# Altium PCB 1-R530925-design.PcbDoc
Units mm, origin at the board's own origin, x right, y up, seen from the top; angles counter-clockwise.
Board outline 53.27 x 52.14 mm, 4 copper layers (Top Layer, Mid-Layer 1, Mid-Layer 2, Bottom Layer); 97 components, 88 nets, 315 pads, 181 vias.
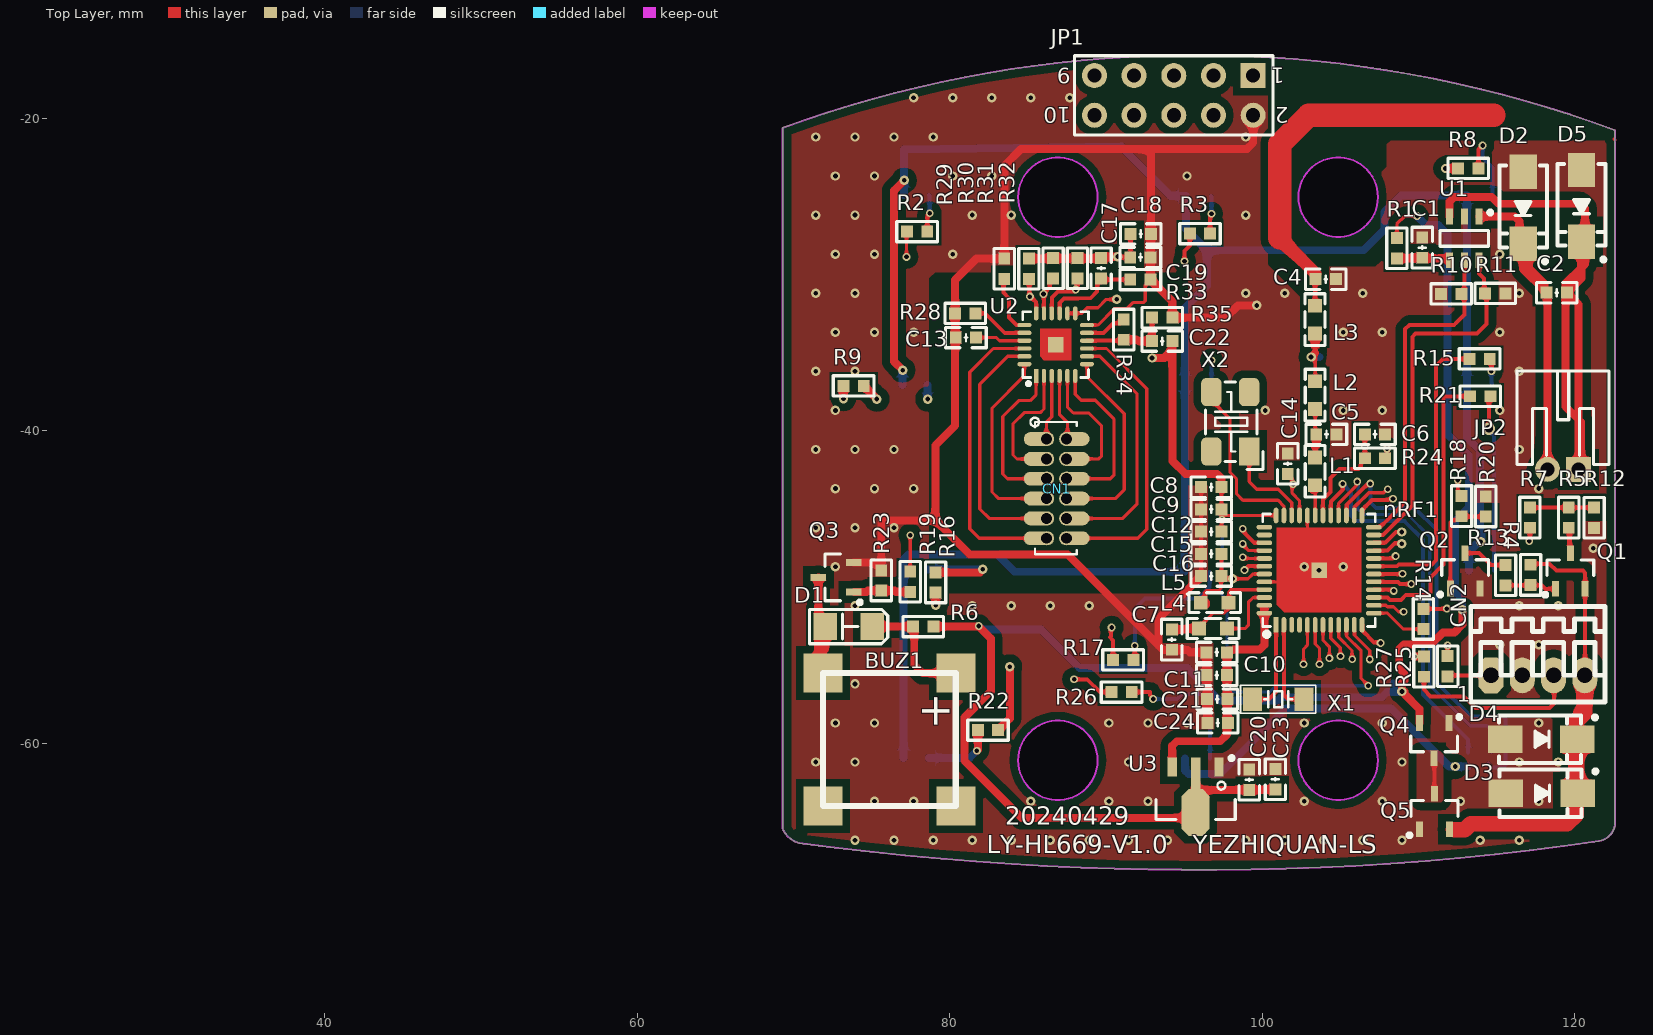
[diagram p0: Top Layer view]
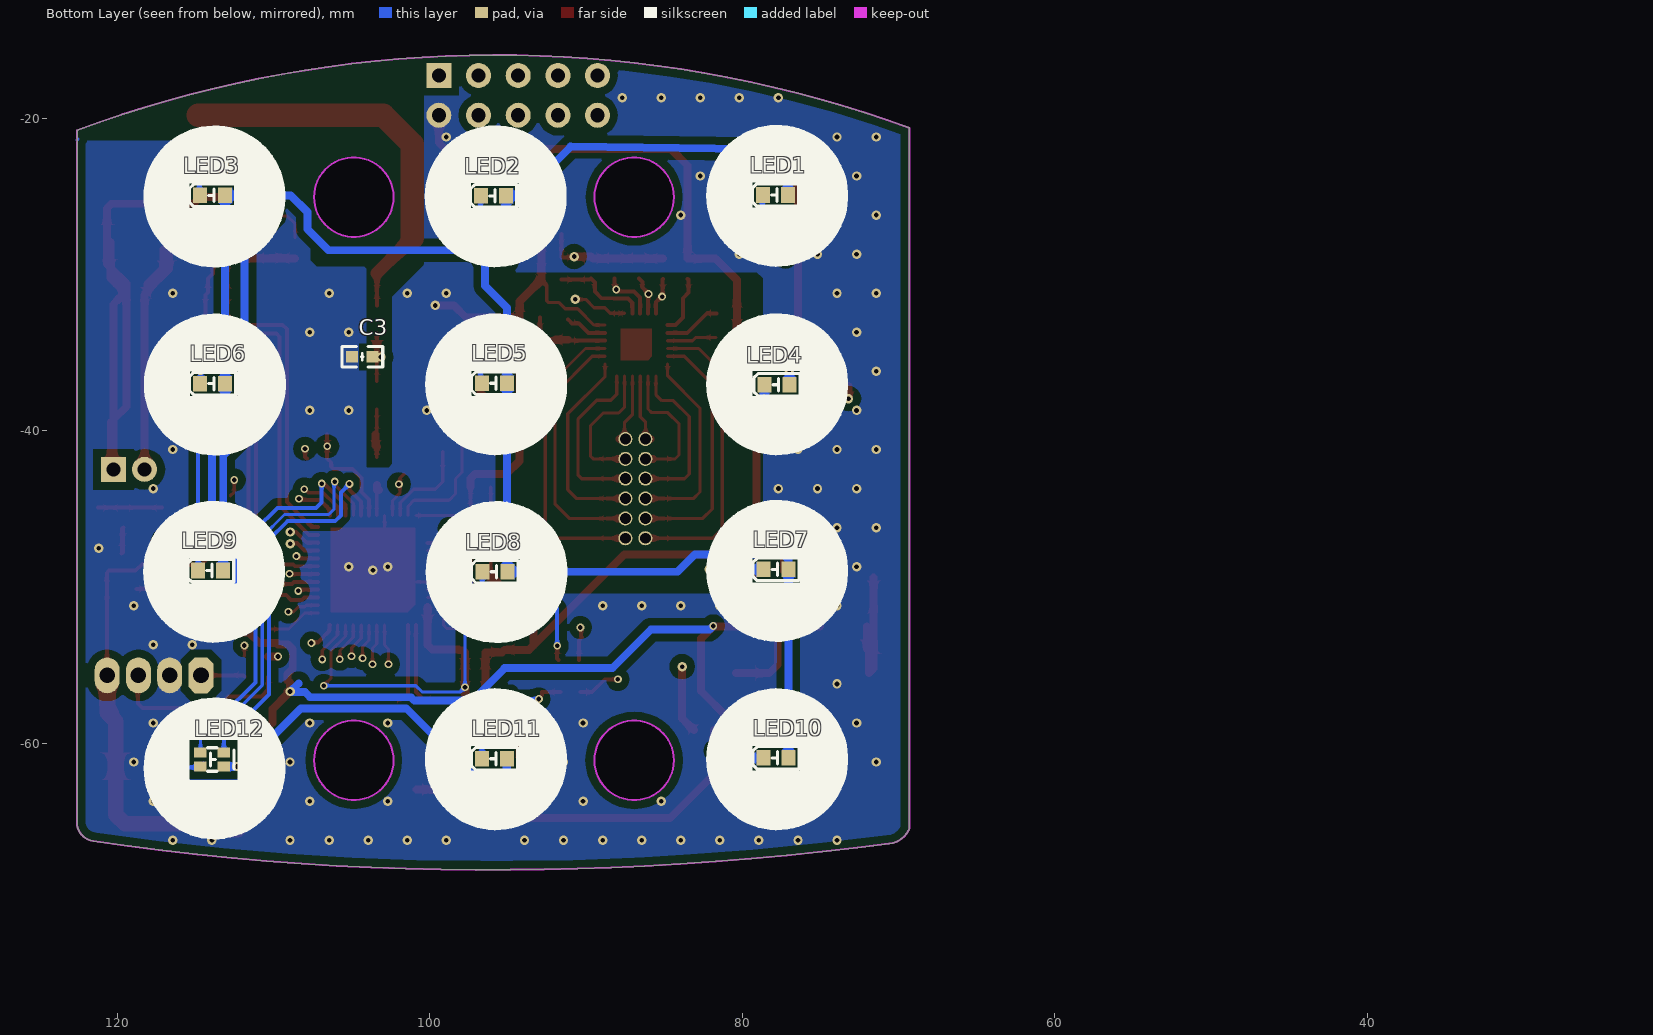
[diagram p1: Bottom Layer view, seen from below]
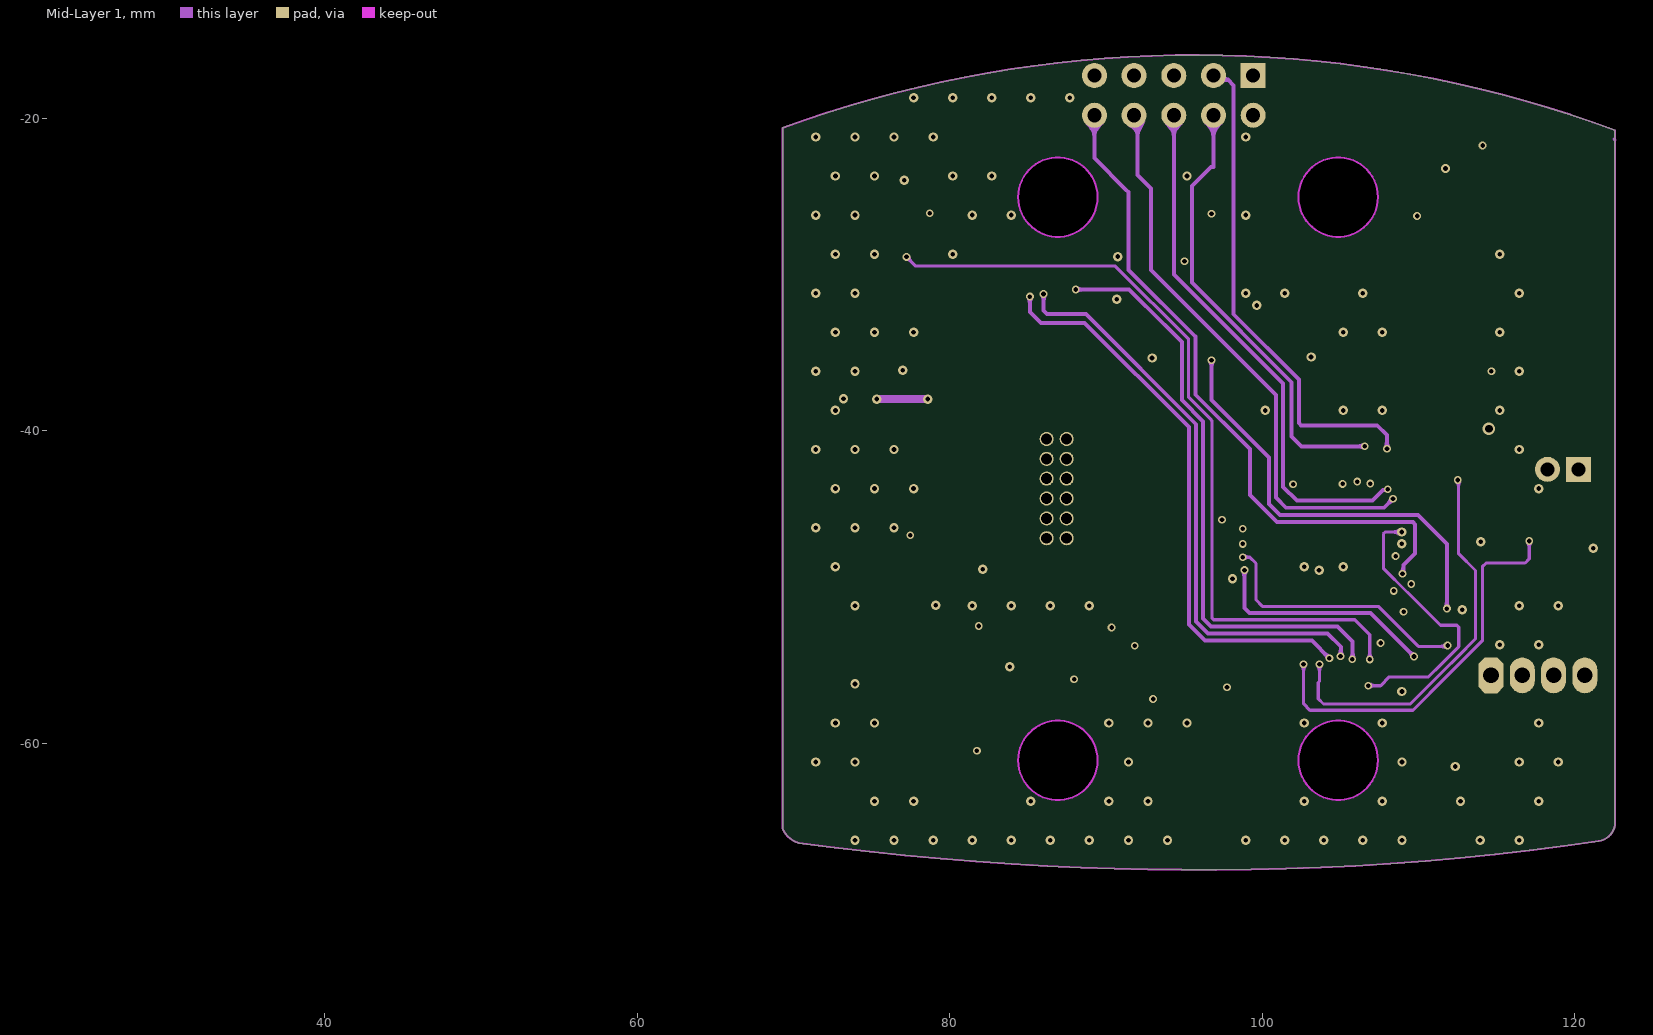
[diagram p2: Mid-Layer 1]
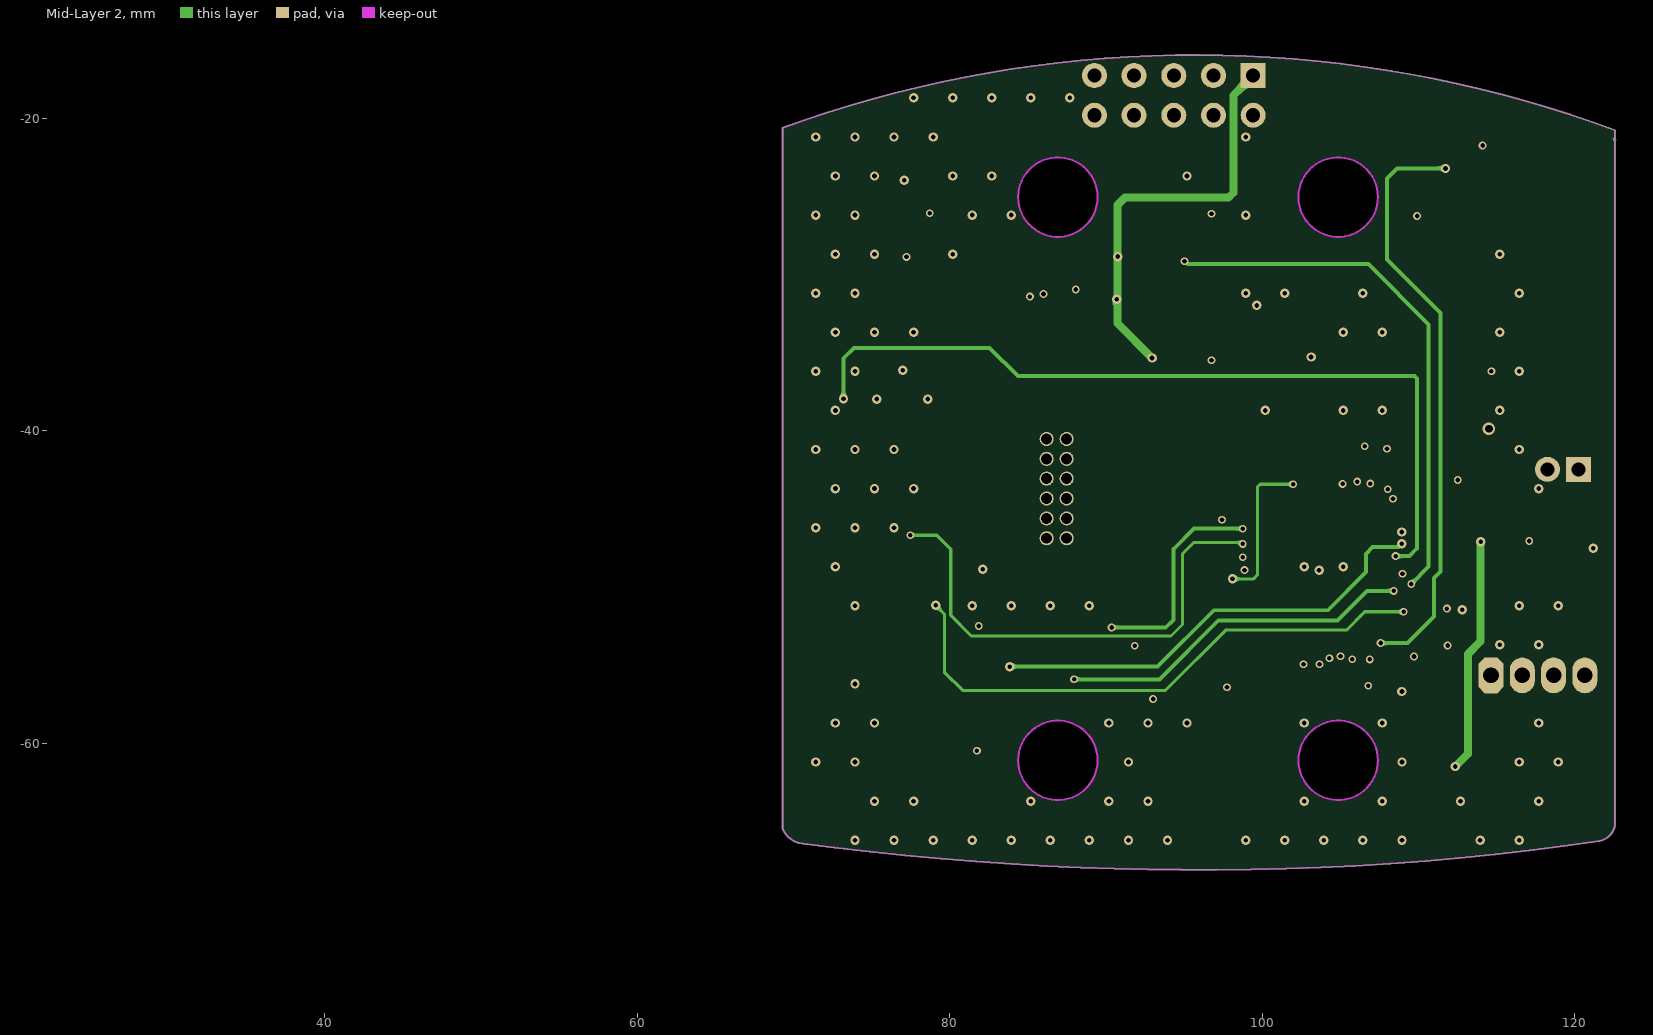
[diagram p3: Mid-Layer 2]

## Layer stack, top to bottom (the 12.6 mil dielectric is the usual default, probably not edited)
Top Layer: signal copper 0.0356
Dielectric: core 0.32, FR-4, Dk 4.8
Mid-Layer 1: signal copper 0.0356
Dielectric: prepreg 0.32, FR-4, Dk 4.8
Mid-Layer 2: signal copper 0.0356
Dielectric: core 0.32, FR-4, Dk 4.8
Bottom Layer: signal copper 0.0356

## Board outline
70.353,-66.388 cw(c70.831,-64.793) 69.301,-65.452 69.301,-20.62 cw(c95.728,-93.172) 122.567,-20.772 122.567,-65.212 cw(c121.341,-65.029) 121.523,-66.256 cw(c96.719,100.307) 94.816,-68.082 cw(c94.76,92.142) 86.241,-67.855 cw(c97.151,137.032)
cut-out: 102.316,-61.091 ccw(c104.857,-61.091) 104.857,-63.633 ccw(c104.857,-61.091) 107.399,-61.091 ccw(c104.857,-61.091) 104.857,-58.55 ccw(c104.857,-61.091)
cut-out: 84.377,-61.091 ccw(c86.918,-61.091) 86.918,-63.633 ccw(c86.918,-61.091) 89.46,-61.091 ccw(c86.918,-61.091) 86.918,-58.55 ccw(c86.918,-61.091)
cut-out: 84.377,-25.05 ccw(c86.918,-25.05) 86.918,-27.592 ccw(c86.918,-25.05) 89.46,-25.05 ccw(c86.918,-25.05) 86.918,-22.508 ccw(c86.918,-25.05)
cut-out: 102.316,-25.05 ccw(c104.857,-25.05) 104.857,-27.592 ccw(c104.857,-25.05) 107.399,-25.05 ccw(c104.857,-25.05) 104.857,-22.508 ccw(c104.857,-25.05)

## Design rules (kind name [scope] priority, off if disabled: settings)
Clearance [All] p1: gap=0.5
FanoutControl Fanout_Small [All] p1 off: bgadir=Out bgaviamode=Centered fanoutstyle=Auto fanoutdirection=Alternating viagrid=0.025 // Protel DXP Scope 1 Expression Was: (CompPinCount < 5)   Fanout_Small (Default Rule)
FanoutControl Fanout_Default [All] p2: bgadir=Out bgaviamode=Centered fanoutstyle=Auto fanoutdirection=Alternating viagrid=0.025 // Fanout_Default (Default Rule)
FanoutControl Fanout_SOIC [All] p3 off: bgadir=Out bgaviamode=Centered fanoutstyle=Auto fanoutdirection=Alternating viagrid=0.025 // Protel DXP Scope 1 Expression Was: IsSOIC   Fanout_SOIC (Default Rule)
FanoutControl Fanout_BGA [All] p4 off: bgadir=Out bgaviamode=Centered fanoutstyle=Auto fanoutdirection=Alternating viagrid=0.025 // Protel DXP Scope 1 Expression Was: IsBGA   Fanout_BGA (Default Rule)
FanoutControl Fanout_LCC [All] p5 off: bgadir=Out bgaviamode=Centered fanoutstyle=Auto fanoutdirection=Alternating viagrid=0.025 // Protel DXP Scope 1 Expression Was: IsLCC   Fanout_LCC (Default Rule)
HoleToHoleClearance [All] p1: gap=0.178 allowstackedmicrovias=TRUE
MinimumSolderMaskSliver [All] p1: minsoldermaskwidth=0.102
PlaneConnect [All] p1: planeconnectstyle=Direct reliefexpansion=0.508 reliefentries=4 reliefconductorwidth=0.254 reliefairgap=0.254
PolygonConnect [All] p1: connectstyle=Direct reliefconductorwidth=0.254 reliefentries=4 polygonreliefangle="90 Angle" airgapwidth=0.254
RoutingVias [All] p1: holewidth=0.3 width=0.6 viastyle="Through Hole" minholewidth=0.1 minwidth=0.1 maxholewidth=0.711 maxwidth=1
SilkToSilkClearance [All] p1: silktosilkclearance=0
SilkToSolderMaskClearance SilkscreenOverComponentPads [IsPad] p1: minsilkscreentomaskgap=0 clearancetoexposedcopper=TRUE
SolderMaskExpansion [All] p1: expansion=0.102
Width [All] p1: maxlimit=2.54 minlimit=0.203 preferedwidth=0.508
18 further rules are at their usual default settings.

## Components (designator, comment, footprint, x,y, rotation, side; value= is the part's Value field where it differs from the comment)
BUZ1 "" BUZ-SMD8.5*8.5*3 80.391,-55.508 r270 top
C1 "10uF" "C 0603_L" 110.236,-28.281 r270 top
C2 "100nF" "C 0603_L" 118.847,-31.166 r0 top
C3 "2.0pF" "C 0603_L" 104.309,-35.267 r180 bottom
C4 "0.3pF" "C 0603_L" 104.053,-30.302 r180 top
C5 "1.5pF" "C 0603_L" 104.104,-40.234 r180 top
C6 "3.9pF" "C 0603_L" 107.209,-40.234 r180 top
C7 "2.2uF" "C 0603_L" 94.209,-53.365 r90 top
C8 "100nF" "C 0603_L" 96.738,-43.612 r0 top
C9 "100nF" "C 0603_L" 96.738,-45.034 r0 top
C10 "10uF" "C 0603_L" 97.089,-54.178 r0 top
C11 "0.1uF" "C 0603_L" 97.089,-55.641 r0 top
C12 "100nF" "C 0603_L" 96.738,-46.457 r180 top
C13 "5PF" "C 0603_L" 81.036,-34.036 r0 top
C14 "10nF" "C 0603_L" 101.625,-42.113 r90 top
C15 "10nF" "C 0603_L" 96.738,-47.879 r180 top
C16 "2.2uF" "C 0603_L" 96.738,-49.302 r180 top
C17 "0.1uF" "C 0603_L" 89.687,-29.601 r90 top
C18 "10uF" "C 0603_L" 92.217,-27.407 r180 top
C19 "0.1uF" "C 0603_L" 92.202,-28.905 r180 top
C20 "10uF" "C 0603_L" 99.162,-62.332 r270 top
C21 "10uF" "C 0603_L" 97.119,-57.175 r0 top
C22 "820pF" "C 0603_L" 93.599,-34.265 r0 top
C23 "0.1uF" "C 0603_L" 100.84,-62.305 r270 top
C24 "0.1uF" "C 0603_L" 97.145,-58.699 r0 top
CN1 "Header 6X2" 48 86.211,-46.872 r90 top locked
CN2 "PH2.0*4Pin带焊针线" JC20-4Y 114.637,-55.651 r0 top
D1 "IN4148" SOD-123/1206 73.534,-52.527 r180 top
D2 "SMBJ5.0A" SMA 116.688,-25.73 r270 top
D3 "SMBJ5.0A" SMA 117.881,-63.195 r0 top
D4 "SMBJ5.0A" SMA 117.856,-59.741 r0 top
D5 "SMBJ5.0A" SMA 120.421,-25.617 r270 top
JP1 "HEADER 5X2" HDR2.54-LI-2x5P 94.336,-18.542 r180 top
JP2 "HDR-1X2" PH2.0-WI-2P 119.244,-42.469 r180 top
L1 "2.7nH" "L 0603" 103.383,-42.596 r90 top
L2 "3.5nH" "L 0603" 103.383,-37.719 r90 top
L3 "3.5nH" "L 0603" 103.375,-32.889 r90 top
L4 "4.7uH" "L 0603" 96.85,-52.654 r180 top
L5 "FB1" "L 0603" 96.952,-51.003 r180 top
LED1 "" LED-0603-Blue 77.876,-24.917 r180 bottom
LED2 "" LED-0603-Blue 95.91,-24.968 r180 bottom
LED3 "" LED-0603-Blue 113.894,-24.943 r180 bottom
LED4 "" LED-0603-Blue 77.775,-37.059 r180 bottom
LED5 "" LED-0603-Blue 95.847,-36.957 r180 bottom
LED6 "" LED-0603-Blue 113.894,-36.982 r180 bottom
LED7 "" LED-0603-Blue 77.838,-48.87 r180 bottom
LED8 "" LED-0603-Blue 95.834,-49.022 r180 bottom
LED9 "" LED-0603-Blue 114.021,-48.946 r180 bottom
LED10 "" LED-0603-Blue 77.851,-60.935 r180 bottom
LED11 "" LED-0603-Blue 95.86,-60.985 r180 bottom
LED12 "TJ-S1615CY6TGLCCSRGB-A5" LED-1615-三色 113.919,-61.036 r90 bottom
nRF1 "U2" "QFN48 7X7_M" 103.632,-48.92 r0 top
Q1 "AO3401(A19T)" SOT23-3L#1 119.71,-48.971 r0 top
Q2 "8050" SOT23-3L#2 112.979,-48.953 r0 top
Q3 "8050" SOT23-3L#2 72.72,-49.378 r90 top
Q4 "AO3401(A19T)" SOT23-3L#1 110.998,-59.842 r180 top
Q5 "AO3401(A19T)" SOT23-3L#1 111.013,-64.364 r0 top
R1 "1R" "R 0603_L" 108.61,-28.321 r270 top
R2 "1KΩ±1%-0402" "R 0603_L" 77.912,-27.254 r180 top
R3 "1KΩ±1%-0402" "R 0603_L" 96.012,-27.381 r180 top
R4 "100KΩ±5%-0402" "R 0603_L" 117.17,-49.225 r270 top
R5 "22KΩ±5%-0402" "R 0603_L" 119.609,-45.557 r90 top
R6 "100Ω±5%" "R 0603_L" 78.308,-52.527 r0 top
R7 "1KΩ±5%-0402" "R 0603_L" 117.119,-45.557 r270 top
R8 "1KΩ±1%-0402" "R 0603_L" 113.182,-23.216 r180 top
R9 "1KΩ±1%-0402" "R 0603_L" 73.848,-37.135 r180 top
R10 "10KR" "R 0603_L" 112.088,-31.246 r0 top
R11 "10KR" "R 0603_L" 114.91,-31.217 r180 top
R12 "10KΩ±5%-0402" "R 0603_L" 121.234,-45.568 r270 top
R13 "1KΩ±5%-0402" "R 0603_L" 115.57,-49.24 r90 top
R14 "1KΩ±1%-0402" "R 0603_L" 110.312,-52.045 r270 top
R15 "1KΩ±1%-0402" "R 0603_L" 113.904,-35.408 r180 top
R16 "1KΩ±1%-0402" "R 0603_L" 79.096,-49.708 r270 top
R17 "1KΩ±1%-0402" "R 0603_L" 91.095,-54.661 r180 top
R18 "1KΩ±5%-0402" "R 0603_L" 112.751,-44.821 r90 top
R19 "1KΩ±1%-0402" "R 0603_L" 77.47,-49.667 r90 top
R20 "10KΩ±5%-0402" "R 0603_L" 114.3,-44.846 r270 top
R21 "1KΩ±1%-0402" "R 0603_L" 113.944,-37.795 r180 top
R22 "1KΩ±1%-0402" "R 0603_L" 82.448,-59.157 r0 top
R23 "10KΩ±1%-0402" "R 0603_L" 75.616,-49.581 r270 top
R24 "1KΩ±5%-0402" "R 0603_L" 107.209,-41.762 r180 top
R25 "1KΩ±5%-0402" "R 0603_L" 111.862,-55.067 r90 top
R26 "1KΩ±1%-0402" "R 0603_L" 90.993,-56.718 r180 top
R27 "1KΩ±5%-0402" "R 0603_L" 110.338,-55.093 r90 top
R28 "510KΩ±5%-0402" "R 0603_L" 80.99,-32.487 r0 top
R29 "2MΩ±5%-0402" "R 0603_L" 83.49,-29.631 r270 top
R30 "10KΩ±5%-0402" "R 0603_L" 85.065,-29.631 r90 top
R31 "10KΩ±5%-0402" "R 0603_L" 86.614,-29.606 r90 top
R32 "10KΩ±5%-0402" "R 0603_L" 88.163,-29.606 r90 top
R33 "330KΩ±5%-0402" "R 0603_L" 92.202,-30.328 r0 top
R34 "510KΩ±5%-0402" "R 0603_L" 91.135,-33.528 r90 top
R35 "2MΩ±5%-0402" "R 0603_L" 93.599,-32.766 r0 top
U1 "SA8316" SOT23-6L 112.928,-27.686 r180 top
U2 "TSM12S QFN24" "QFN24 4x4_N" 86.778,-34.487 r0 top
U3 "6209A SOT89" SOT89_L 95.731,-61.822 r180 top
X1 "32.786KHz" "OSC 3215-2P" 101.016,-57.175 r0 top
X2 "32MHZ" "OSC 5032-4P" 98.012,-39.426 r90 top

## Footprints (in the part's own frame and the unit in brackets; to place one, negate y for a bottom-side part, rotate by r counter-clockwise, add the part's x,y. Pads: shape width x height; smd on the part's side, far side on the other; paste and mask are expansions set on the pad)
48 [mm]
  oval 0.89x1.95 smd mask+0.05: 1(6.342,0.499) 2(5.072,0.499) 3(3.802,0.499) 4(2.532,0.499) 5(1.262,0.499) 6(-0.008,0.499) 7(-0.008,-1.759) 8(1.262,-1.759) 9(2.532,-1.759) 10(3.802,-1.759) 11(5.072,-1.759) 12(6.342,-1.759)
  round 0.9 hole 0.7 mask+0.05: 1(6.343,0.012) 2(5.073,0.012) 3(3.803,0.012) 4(2.533,0.012) 5(1.263,0.012) 6(-0.007,0.012) 7(-0.007,-1.271) 8(1.263,-1.271) 9(2.533,-1.271) 10(3.803,-1.271) 11(5.073,-1.271) 12(6.343,-1.271)
  silkscreen extent -1.03,-1.91 7.7,1.05
BUZ-SMD8.5*8.5*3 [mm]
  rect 2.5x2.5 smd: 1(0,0) 2(0,-8.5) ""(8.5,0) ""(8.5,-8.5)
  silkscreen extent 0,-8.5 8.5,0, body extent -0.19,-8.52 8.31,-0.02, height 3
"C 0603_L" [mil] "无极性贴片电容"
  rect 30x30 smd: 1(-25.59,0) 2(25.59,0)
  silkscreen extent -51,-26 51,26, body extent -31,-16 31,16, height 32
HDR2.54-LI-2x5P [mm] "双排排针，5x2脚"
  rect 1.6x1.6 hole 0.9: 1(-5.08,-1.27)
  round 1.6 hole 0.9: 2(-5.08,1.27) 3(-2.54,-1.27) 4(-2.54,1.27) 5(0,-1.27) 6(0,1.27) 7(2.54,-1.27) 8(2.54,1.27) 9(5.08,-1.27) 10(5.08,1.27)
  silkscreen extent -6.35,-2.54 6.35,2.54, body extent -6.35,-2.54 6.35,2.54, height 8.5
JC20-4Y [mm]
  oct 1.6x2.3 hole 1: 1(0,0)
  oval 1.6x2.3 hole 1: 2(2,0) 3(4,0) 4(6,0)
  silkscreen extent -1.3,-1.7 7.3,4.4, body extent -1.43,-1.86 7.43,4.55, height 3.5
"L 0603" [mil] "小功率贴片电感"
  rect 35x35 smd: 1(-35,0) 2(35,0)
  silkscreen extent -65,-25 65,25, body extent -31,-16 31,16, height 31
LED-0603-Blue [mm]
  rect 0.9x1 smd: 1(0.8,0) 2(-0.8,0)
  silkscreen extent -1.48,-0.72 1.48,0.72, body extent -0.81,-0.4 0.81,0.4, height 0.6
LED-1615-三色 [mm]
  rect 0.65x0.8 smd: 1(-0.45,-0.75) 2(0.45,-0.75) 3(0.45,0.75) 4(-0.45,0.75)
  silkscreen extent -0.75,-1.4 0.75,0.3, body extent -0.75,-0.8 0.75,0.8, height 0.55
"OSC 3215-2P" [mm] "3.2*1.5*0.6mm(长宽高)"
  rect 1.2x1.5 smd: 1(-1.65,0) 2(1.65,0)
  silkscreen extent -2.41,-0.89 2.41,0.89, body extent -1.6,-0.75 1.6,0.75, height 0.61
"OSC 5032-4P" [mm] "5mm*3.2mm*0.8mm(长*宽*高)"
  rect 1.8x1.3 smd: 1(-1.9,-1.15)
  rrect50% 1.8x1.3 smd: 2(1.9,-1.15) 3(1.9,1.272) 4(-1.9,1.272)
  silkscreen extent -3.05,-2.03 2.54,1.65, body extent -2.5,-1.6 2.5,1.6, height 0.86
PH2.0-WI-2P [mm] "长：5.9mm，宽：6mm，高：4.7mm"
  rect 1.6x1.6 hole 0.9: 1(-1,0)
  round 1.6 hole 0.9: 2(1,0)
  silkscreen extent -2.95,-6.3 2.95,-0.3, body extent -2.95,-6.3 2.95,0.3, height 4.75
"QFN24 4x4_N" [mm] "24脚，长x宽x高：4x4x1mm，脚距：0.5mm"
  rect 0.28x0.9 smd: 1(-1.25,-2)
  oval 0.28x0.9 smd: 2(-0.75,-2) 3(-0.25,-2) 4(0.25,-2) 5(0.75,-2) 6(1.25,-2) 13(1.25,2) 14(0.75,2) 15(0.25,2) 16(-0.25,2) 17(-0.75,2) 18(-1.25,2)
  oval 0.9x0.28 smd: 7(2,-1.25) 8(2,-0.75) 9(2,-0.25) 10(2,0.25) 11(2,0.75) 12(2,1.25) 19(-2,1.25) 20(-2,0.75) 21(-2,0.25) 22(-2,-0.25) 23(-2,-0.75) 24(-2,-1.25)
  rect 1x1 smd: 25(0,0)
  Top Layer region: -1,1 1,1 1,-1 -0.75,-1 -1,-0.75
  silkscreen extent -2.11,-2.6 2.11,2.11, body extent -2.01,-2.01 2.01,2.01, height 0.95
"QFN48 7X7_M" [mm] "48脚，长x宽x高：7x7x1mm，脚距：0.5mm"
  rect 0.3x1 smd: 1(-2.75,-3.5)
  oval 0.3x1 smd: 2(-2.25,-3.5) 3(-1.75,-3.5) 4(-1.25,-3.5) 5(-0.75,-3.5) 6(-0.25,-3.5) 7(0.25,-3.5) 8(0.75,-3.5) 9(1.25,-3.5) 10(1.75,-3.5) 11(2.25,-3.5) 12(2.75,-3.5) 25(2.75,3.5) 26(2.25,3.5) 27(1.75,3.5) 28(1.25,3.5) 29(0.75,3.5) 30(0.25,3.5) 31(-0.25,3.5) 32(-0.75,3.5) 33(-1.25,3.5) 34(-1.75,3.5) 35(-2.25,3.5) 36(-2.75,3.5)
  oval 1x0.3 smd: 13(3.5,-2.75) 14(3.5,-2.25) 15(3.5,-1.75) 16(3.5,-1.25) 17(3.5,-0.75) 18(3.5,-0.25) 19(3.5,0.25) 20(3.5,0.75) 21(3.5,1.25) 22(3.5,1.75) 23(3.5,2.25) 24(3.5,2.75) 37(-3.5,2.75) 38(-3.5,2.25) 39(-3.5,1.75) 40(-3.5,1.25) 41(-3.5,0.75) 42(-3.5,0.25) 43(-3.5,-0.25) 44(-3.5,-0.75) 45(-3.5,-1.25) 46(-3.5,-1.75) 47(-3.5,-2.25) 48(-3.5,-2.75)
  rect 1x1 smd mask+0.051: 49(0,0)
  Top Layer region: -2.7,2.7 2.7,2.7 2.7,-2.7 -2.214,-2.7 -2.7,-2.214
  silkscreen extent -3.6,-4.25 3.6,3.6, body extent -3.51,-3.51 3.51,3.51, height 0.95
"R 0603_L" [mil] "1/10W贴片电阻"
  rect 30x30 smd: 1(-25.59,0) 2(25.59,0)
  silkscreen extent -51,-26 51,26, body extent -31,-16 32,16, height 16
SMA [mm] "4.5x2.6*2.2mm（长宽高，不包括引脚）"
  rect 2.2x1.75 smd: 1(-2.3,0) 2(2.3,0)
  silkscreen extent -2.7,-1.52 3.56,1.52, body extent -2.53,-1.3 2.58,1.3, height 2.15
SOD-123/1206 [mm] "4148"
  rect 1.5x1.7 smd: 1(1.5,0) 2(-1.5,0)
  silkscreen extent -2.5,-1.1 2.5,1.1, body extent -1.85,-0.8 1.85,0.8, height 1.28
SOT23-3L#1 [mm] "3x1.3x1mm(长宽高)"
  rect 0.45x1 smd: 1(-0.95,-1.143) 2(0.95,-1.143) 3(0,1.125)
  silkscreen extent -1.72,-1.65 1.5,0.7, body extent -1.5,-1.2 1.5,1.2, height 1.05
SOT23-3L#2 [mm] "3x1.3x1mm(长宽高)"
  rect 0.45x1 smd: B(-0.95,-1.143) C(0,1.125) E(0.95,-1.143)
  silkscreen extent -1.72,-1.65 1.5,0.7, body extent -1.5,-1.2 1.5,1.2, height 1.05
SOT23-6L [mm] "3x1.6x1.1mm(长宽高)"
  rect 0.45x1 smd: 1(-0.95,-1.397) 2(0,-1.397) 3(0.95,-1.397) 4(0.95,1.397) 5(0,1.397) 6(-0.95,1.397)
  silkscreen extent -1.78,-1.78 1.55,0.51, body extent -1.5,-1.4 1.5,1.4, height 1.15
SOT89_L [mm] "4.6x4.3x1.6mm(长宽高)"
  rect 0.6x1.2 smd: 1(-1.5,-0.303) 3(1.5,-0.303)
  oct 1.8x3 smd: 2(0,2.616)
  rect 0.6x2.1 smd: 2(0,0.127)
  silkscreen extent -2.54,-1 2.54,3.05, body extent -2.3,-0.88 2.3,3.42, height 1.6

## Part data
BUZ1: library part BUZZER, "Buzzer"
C1 C2 C3 C4 C5 C6 C7 C8 C9 C10 C11 C12 C13 C14 C15 C16 C17 C18 C19 C20 C21 C22 C23 C24: library part CAP_1, "Capacitor"
CN1: library part "Header  6X2", "6*2P接插件"
CN2: library part CON4, "Connector"
D1: library part DIODE, "Diode"
D2 D3 D4 D5: library part TVS-1, "SMB"
JP2: library part "Header 2", "2P接插件"
L1 L2 L3 L4 L5: library part Inductor, "电感"
LED1 LED2 LED3 LED4 LED5 LED6 LED7 LED8 LED9 LED10 LED11: library part LED
LED12: "1615共阴三色RGB  SMD1615燈珠共陰RGB  统佳"
nRF1: library part Component_1
Q1 Q4 Q5: library part "MOSFET P"
R1 R2 R3 R4 R5 R6 R7 R8 R9 R10 R11 R12 R13 R14 R15 R16 R17 R18 R19 R20 R21 R22 R23 R24 R25 R26 R27 R28 R29 R30 R31 R32 R33 R34 R35: library part RES1
U1: library part MX113H, "马达驱动IC芯片H桥驱动"
U3: library part 贴片三端稳压管6209A
X1 X2: library part Crystal

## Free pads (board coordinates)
  round 0.001 on Mech1: 1(24.156,-18.291) 1(84.856,-75.264)

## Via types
v1: diameter 0.6, hole 0.3, Top Layer to Bottom Layer, 130 vias
v2: diameter 0.5, hole 0.3, Top Layer to Bottom Layer, 50 vias
v3: diameter 0.8, hole 0.5, Top Layer to Bottom Layer, 1 vias

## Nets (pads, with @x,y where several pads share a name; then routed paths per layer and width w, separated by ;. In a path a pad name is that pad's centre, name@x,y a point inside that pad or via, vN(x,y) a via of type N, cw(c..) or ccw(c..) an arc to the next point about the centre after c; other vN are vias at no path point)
ADC_EN: nRF1.6 R18.2 | length 28.6
  Top Layer w0.203: nRF1.6 103.382,-53.649 103.657,-53.924 v2(103.657,-54.94) ; v2(112.507,-43.148) 112.507,-43.927 R18.2
  Mid-Layer 1 w0.203: v2(103.657,-54.94) 103.657,-56.047 103.581,-56.123 103.581,-57.15 103.913,-57.482 109.472,-57.482 111.582,-55.372 112.493,-54.461 ; 112.493,-54.461 113.64,-53.315 113.64,-48.946 112.564,-47.87 112.564,-43.205 v2(112.507,-43.148)
ANT: L1.1 nRF1.31 | length 2.1
  Top Layer w0.203: L1.1@103.251,-43.79 103.382,-43.921 nRF1.31
  Top Layer w0.508: L1.1@103.251,-43.79 103.383,-43.79 L1.1
BAT+: C20.2 C23.2 Q4.2 R1.1 R6.2 U3.2 | length 107.9
  Top Layer w0.203: R1.1 108.61,-26.765 109.112,-26.264 v2(109.906,-26.264)
  Top Layer w0.508: R6.2 81.856,-52.527 82.626,-53.298 82.626,-56.667 80.948,-58.345 80.948,-61.114 84.606,-64.771 95.731,-64.771 95.731,-64.438 U3.2@95.731,-62.699 ; U3.2@95.731,-61.949 U3.2@95.731,-62.699 ; C23.2 99.999,-62.955 99.973,-62.982 C20.2 96.014,-62.982 U3.2@95.731,-62.699 ; v1(108.933,-56.688) 108.951,-56.67 108.951,-56.112 109.091,-55.971 109.091,-55.55 108.763,-55.221 108.763,-53.968 109.06,-53.67 109.706,-53.67 109.782,-53.594 110.871,-53.594 111.557,-52.908 112.293,-52.908 112.801,-52.4 v1(112.801,-51.46) ; v1@109.091,-56.688 109.091,-56.846 110.048,-57.803 Q4.2
  Bottom Layer w0.508: v2(81.856,-52.488) 82.098,-52.73 85.852,-52.73 88.316,-55.194 95.199,-55.194 97.276,-57.271 100.986,-57.271 101.205,-57.052 107.645,-57.052 107.991,-56.705 108.915,-56.705 v1(108.933,-56.688) 108.908,-56.688 108.38,-56.159 ; v2(109.906,-26.264) 110.49,-26.848 111.277,-26.848 111.836,-27.407 111.836,-40.208 113.211,-41.583 113.211,-44.904 112.317,-45.798 112.317,-50.29 112.784,-50.757 112.784,-51.443 v1(112.801,-51.46)
BAT_ADC: nRF1.5 R7.2 | length 28.6
  Top Layer w0.2: v2(102.641,-54.94) 102.641,-53.962 102.882,-53.721 nRF1.5
  Top Layer w0.254: v2(117.079,-47.06) 117.119,-47.019 R7.2
  Mid-Layer 1 w0.203: v2(102.641,-54.94) 102.641,-55.604 102.641,-57.48 103.046,-57.885 109.639,-57.885 111.749,-55.775 112.896,-54.628 114.083,-53.442 114.083,-48.706 114.325,-48.463 116.815,-48.463 117.079,-48.199 117.079,-47.498 v2(117.079,-47.06)
BUZ: nRF1.40 R19.2 | length 35.5
  Top Layer w0.203: R19.2 v2(77.47,-46.685) ; v2(98.745,-47.237) 98.721,-47.261 99.131,-47.67 nRF1.40
  Mid-Layer 2 w0.203: v2(77.47,-46.685) 79.172,-46.685 80.061,-47.574 80.061,-51.816 81.382,-53.137 94.158,-53.137 94.894,-52.4 94.894,-47.879 95.631,-47.142 98.628,-47.142 98.723,-47.237 v2(98.745,-47.237)
DCC: L4.1 nRF1.46 | length 4.1
  Top Layer w0.203: L4.1 98.908,-52.654 99.111,-52.451 99.111,-50.978 99.418,-50.67 nRF1.46
DECA: C14.1 C15.1 C16.1 L5.2 nRF1.33 nRF1.43 | length 20.7
  Top Layer w0.203: L5.2 96.291,-50.775 96.291,-50.36 96.41,-50.241 97.206,-50.241 97.358,-50.089 97.358,-49.331 C16.1 ; L5.2@96.388,-51.135 96.391,-51.132 L5.2@96.393,-51.13 ; C15.1 C16.1 ; nRF1.43 99.387,-49.17 99.085,-49.472 97.559,-49.472 C16.1 ; C14.1 C14.1@101.905,-43.043 ; v2(101.971,-43.42) 101.915,-43.476 101.915,-43.053 C14.1@101.905,-43.043 ; nRF1.33 102.382,-44.47 101.905,-43.993 C14.1@101.905,-43.043
  Top Layer w0.508: L5.2 96.391,-51.003 96.391,-51.132 96.391,-51.135 L5.2@96.388,-51.135
  Mid-Layer 2 w0.203: v1(98.095,-49.479) 99.441,-49.479 99.695,-49.225 99.695,-43.586 99.861,-43.42 v2(101.971,-43.42)
IN_BAT+6V: CN2.4 D3.2 D4.2 Q1.2 Q5.2 R4.1 | length 34
  Top Layer w0.254: R4.1 117.231,-48.514 118.389,-48.514 118.821,-48.946 120.511,-48.946 120.66,-49.095 Q1.2 120.648,-50.126 120.648,-55.64 CN2.4
  Top Layer w0.508: Q5.2 112.293,-65.507 112.293,-65.532 ; D3.2 120.181,-61.495 120.156,-61.469 D4.2 120.156,-58.533 120.156,-57.939 120.637,-57.458 CN2.4
  Top Layer w1: 112.293,-65.532 112.954,-65.532 113.335,-65.151 119.505,-65.151 120.091,-64.565 120.091,-58.598 120.156,-58.533 120.637,-58.052 120.637,-57.458
INT: nRF1.9 R32.1 U2.16 | length 43.6
  Top Layer w0.2: nRF1.9 104.893,-52.432 104.893,-53.22 105.739,-54.066 105.739,-54.594 v2(105.761,-54.616)
  Top Layer w0.254: U2.16 86.528,-31.48 86.919,-31.09 v2@88.015,-31.09 ; v2@88.163,-30.941 R32.1
  Mid-Layer 1 w0.254: v2(88.066,-30.967) 91.469,-30.967 92.515,-32.012 92.54,-32.012 94.853,-34.325 94.853,-38.033 96.215,-39.395 96.215,-52.024 96.716,-52.524 104.823,-52.524 105.778,-53.479 105.778,-54.598 v2(105.761,-54.616)
KEY: nRF1.42 R27.2 | length 16.6
  Top Layer w0.254: v2(98.857,-48.92) 99.116,-48.662 100.123,-48.662 nRF1.42
  Top Layer w0.5: v2(109.707,-54.443) R27.2
  Mid-Layer 1 w0.254: v2(98.857,-48.92) 98.857,-51.333 99.19,-51.667 106.931,-51.667 v2(109.707,-54.443)
LED1: nRF1.11 R2.2 | length 55.1
  Top Layer w0.203: v2(77.234,-28.873) 77.234,-27.283 R2.2 ; nRF1.11 105.901,-52.439 105.901,-53.082 106.876,-54.058 v2(106.876,-54.629)
  Mid-Layer 1 w0.203: v2(77.234,-28.873) 77.825,-29.464 90.598,-29.464 95.282,-34.147 95.282,-37.856 96.691,-39.266 96.774,-39.348 96.774,-51.976 96.893,-52.095 105.918,-52.095 106.876,-53.053 v2(106.876,-54.629)
LED2: nRF1.12 R8.2 | length 40.4
  Top Layer w0.254: nRF1.12 106.397,-52.435 106.397,-52.785 107.151,-53.54 107.522,-53.54 v2(107.569,-53.587)
  Top Layer w0.508: v1(111.724,-23.216) R8.2
  Mid-Layer 2 w0.254: v2(107.569,-53.587) 109.278,-53.587 110.973,-51.892 110.973,-49.428 111.392,-49.009 111.392,-32.467 107.975,-29.051 107.975,-23.851 108.61,-23.216 v1(111.724,-23.216)
LED3: nRF1.13 R14.2 | length 3.6
  Top Layer w0.203: nRF1.13 108.008,-51.67 109.032,-52.695 R14.2
LED4: nRF1.14 R16.2 | length 39.4
  Top Layer w0.203: nRF1.14 107.907,-51.17 108.004,-51.267 108.392,-51.267 108.712,-51.587 v2(109.042,-51.587)
  Top Layer w0.508: v1(79.095,-51.166) R16.2
  Mid-Layer 2 w0.203: v1(79.095,-51.166) 79.658,-51.728 79.658,-55.451 80.82,-56.613 93.802,-56.613 97.66,-52.756 105.385,-52.756 106.553,-51.587 v2(109.042,-51.587)
LED5: nRF1.15 R21.2 | length 18.4
  Top Layer w0.254: nRF1.15 108.013,-50.67 108.167,-50.824 108.865,-50.824 109.195,-50.495 110.621,-50.495 110.769,-50.346 110.769,-49.378 111.579,-48.568 111.579,-37.948 111.732,-37.795 R21.2
LED6: nRF1.16 R26.2 | length 26.9
  Top Layer w0.254: v2(87.96,-55.905) 88.798,-55.905 89.611,-56.718 R26.2 ; nRF1.16 107.135,-50.168 108.405,-50.168 108.407,-50.17 v2(108.407,-50.247)
  Mid-Layer 2 w0.254: v2(87.96,-55.905) 93.421,-55.905 97.18,-52.146 104.8,-52.146 106.699,-50.247 v2(108.407,-50.247)
LED7: nRF1.17 R3.2 | length 38.7
  Top Layer w0.254: v2(95.021,-29.159) 95.021,-28.499 95.362,-28.158 R3.2 ; nRF1.17 108.671,-49.67 108.81,-49.809 109.525,-49.809 v2(109.534,-49.8)
  Mid-Layer 2 w0.254: v2(95.021,-29.159) 95.199,-29.337 106.782,-29.337 110.638,-33.193 110.638,-48.697 v2(109.534,-49.8)
LED8: nRF1.20 R9.2 | length 55.1
  Top Layer w0.254: nRF1.20 108.336,-48.17 108.482,-48.024 v2(108.533,-48.024)
  Top Layer w0.508: v1(73.198,-37.943) R9.2
  Mid-Layer 2 w0.254: v1(73.198,-37.943) 73.198,-35.361 73.863,-34.696 82.55,-34.696 84.353,-36.5 109.735,-36.5 109.884,-36.649 109.884,-47.546 109.405,-48.024 v2(108.533,-48.024)
LED9: nRF1.19 R15.2 | length 18.9
  Top Layer w0.254: nRF1.19 108.629,-48.67 108.734,-48.565 110.846,-48.565 111.125,-48.285 111.125,-35.839 111.557,-35.408 R15.2
LED10: nRF1.39 R17.2 | length 17.8
  Top Layer w0.254: v2(90.356,-52.585) 90.356,-52.618 90.309,-52.665 90.309,-53.15 90.246,-53.213 90.445,-53.412 R17.2 ; v2@98.745,-46.266 98.667,-46.343 99.494,-47.17 nRF1.39
  Mid-Layer 2 w0.254: v2(90.356,-52.585) 93.82,-52.585 94.31,-52.095 94.31,-47.581 95.626,-46.266 v2(98.745,-46.266)
LED11: nRF1.21 R22.2 | length 35.4
  Top Layer w0.254: nRF1.21 108.006,-47.67 108.484,-47.193 108.884,-47.193 v1(108.923,-47.232)
  Top Layer w0.508: R22.2 83.845,-58.41 v1(83.845,-55.093)
  Mid-Layer 2 w0.254: v1(83.845,-55.093) 93.294,-55.093 96.901,-51.486 104.191,-51.486 106.629,-49.047 106.629,-47.879 107.061,-47.447 108.708,-47.447 v1(108.923,-47.232)
"LED B": LED12.3 nRF1.28 | length 25.8
  Top Layer w0.203: nRF1.28 104.879,-45.417 104.879,-44.651 106.014,-43.516 106.014,-43.313 v2(106.07,-43.256)
  Bottom Layer w0.203: v2(106.07,-43.256) 106.118,-43.304 106.118,-45.009 106.47,-45.361 109.287,-45.361 110.712,-46.786 110.712,-56.273 113.316,-58.877 114.351,-58.877 114.669,-59.195 LED12.3
"LED G": LED12.4 nRF1.27 | length 28.3
  Top Layer w0.254: nRF1.27 105.391,-45.412 105.391,-44.745 106.303,-43.833 106.309,-43.833 106.759,-43.383 v2(106.909,-43.383)
  Bottom Layer w0.254: v2(106.909,-43.383) 106.909,-44.577 107.264,-44.933 109.75,-44.933 111.141,-46.323 111.141,-56.096 113.34,-58.295 115.421,-58.295 115.57,-58.444 115.57,-61.392 115.418,-61.544 114.727,-61.544 LED12.4 LED12.4@114.471,-61.288
"LED R": LED12.2 nRF1.29 | length 24.6
  Top Layer w0.254: nRF1.29 104.384,-45.418 104.384,-44.539 105.137,-43.786 v2(105.137,-43.401)
  Bottom Layer w0.254: v2(105.137,-43.401) 105.689,-43.953 105.689,-45.415 106.064,-45.79 109.11,-45.79 110.284,-46.964 110.284,-56.867 112.725,-59.309 113.169,-59.753 LED12.2
M+: C2.1 D2.2 JP2.2 U1.1 | length 23.4
  Top Layer w0.5: U1.1 116.154,-26.289 116.459,-26.594 D2.2@116.459,-28.118 ; D2.2 117.039,-28.382 117.039,-29.587 118.065,-30.613 118.065,-31.035 118.065,-31.119 118.244,-31.297 JP2.2
  Top Layer w0.508: D2.2@116.459,-28.118 116.459,-28.246 D2.2@116.688,-28.246 ; D2.2 D2.2@116.688,-28.246 ; C2.1 118.065,-31.035 116.688,-29.657 D2.2@116.688,-28.246
M-: C2.2 D5.2 JP2.1 U1.3 | length 43
  Top Layer w0.5: U1.3 111.978,-25.337 112.271,-25.044 114.681,-25.044 115.113,-25.476 120.357,-25.476 120.65,-25.769 120.65,-29.337 120.421,-29.566 119.405,-30.582 119.405,-38.456 120.244,-39.294 120.396,-39.446 120.396,-42.316 JP2.1
  Top Layer w0.508: JP2.1 120.244,-39.294 120.244,-31.913 C2.2 120.421,-30.241 120.421,-29.566 D5.2
M_IN1: nRF1.24 R10.2 U1.5 | length 21.2
  Top Layer w0.254: nRF1.24 107.494,-46.17 107.517,-46.147 107.548,-46.147 108.255,-45.441 109.144,-44.552 109.144,-33.499 109.42,-33.223 112.268,-33.223 ; 112.395,-33.096 112.928,-32.563 U1.5
M_IN2: nRF1.23 R11.2 U1.6 | length 23.4
  Top Layer w0.254: nRF1.23 107.139,-46.663 107.718,-46.663 109.598,-44.783 109.598,-33.985 109.801,-33.782 113.741,-33.782 114.351,-33.172 114.351,-31.308 R11.2 114.198,-31.155 114.198,-30.251 113.878,-29.931 U1.6
NetBUZ1_1: BUZ1.1 D1.2 R6.1 | length 8
  Top Layer w0.5: D1.2 R6.1 77.724,-52.593 77.724,-54.966 78.266,-55.508 BUZ1.1
NetBUZ1_2: BUZ1.2 D1.1 Q3.C | length 9.3
  Top Layer w0.508: Q3.C 71.595,-55.212 BUZ1.2 71.891,-54.103 72.034,-53.96 D1.1
NetC1_2: C1.2 R1.2 U1.4 | length 4.3
  Top Layer w0.5: R1.2 109.396,-28.971 111.953,-28.971 111.978,-28.996 U1.4
  Top Layer w0.508: 109.396,-28.971 109.437,-28.931 C1.2
NetC3_2: C3.2 L2.2 L3.1 | length 4
  Top Layer w0.203: L2.2 103.383,-35.022 103.383,-33.778 L3.1@103.383,-33.731
  Top Layer w0.508: v1(103.12,-35.284) 103.383,-35.022
  Bottom Layer w0.508: v1(103.12,-35.284) 103.137,-35.267 C3.2
NetC5_2: C5.2 L1.2 L2.1 | length 3.9
  Top Layer w0.203: L1.2 103.383,-41.022 L2.1
  Top Layer w0.508: 103.383,-41.022 103.454,-40.951 C5.2
NetC7_2: C7.2 L4.2 L5.1 nRF1.45 | length 8.5
  Top Layer w0.203: C7.2 95.045,-52.715 95.798,-52.715 95.86,-52.654 95.91,-52.603 96.85,-51.664 97.561,-51.664 97.866,-51.359 97.866,-50.289 97.985,-50.17 nRF1.45
  Top Layer w0.508: 95.045,-52.715 95.107,-52.654 95.86,-52.654 L4.2
NetC13_2: C13.2 U2.21 | length 3.2
  Top Layer w0.203: C13.2 82.982,-34.036 83.182,-34.237 U2.21
NetC17_1: C17.1 R33.1 U2.15 | length 6.2
  Top Layer w0.254: U2.15 87.033,-32.482 87.033,-31.813 87.303,-31.544 88.203,-31.544 88.225,-31.521 89.002,-31.521 89.433,-31.09 89.433,-30.505 C17.1 89.764,-30.328 R33.1
NetC22_1: C22.1 R34.1 R35.1 U2.10 | length 7.7
  Top Layer w0.254: U2.10 92.056,-34.237 92.484,-34.237 92.949,-33.772 R35.1
  Top Layer w0.508: R34.1 91.997,-34.178 92.056,-34.237 92.084,-34.265 C22.1 92.949,-33.772
NetCN2_1: CN2.1 R25.1 | length 2.8
  Top Layer w0.254: R25.1 111.928,-55.651 CN2.1
NetCN2_3: CN2.3 R27.1 | length 11.6
  Top Layer w0.254: R27.1 110.338,-56.566 110.769,-56.998 112.903,-56.998 113.64,-57.734 118.389,-57.734 118.669,-57.455 118.669,-55.683 CN2.3
NetLED1_2: LED1.2 R2.1 | length 2.4
  Top Layer w0.254: R2.1 78.562,-26.238 v2(78.715,-26.086)
  Bottom Layer w0.254: LED1.2 78.715,-24.956 v2(78.715,-26.086)
NetLED2_2: LED2.2 R3.1 | length 2.5
  Top Layer w0.254: R3.1 96.662,-26.223 96.761,-26.124 96.774,-26.111 v2(96.749,-26.111)
  Bottom Layer w0.254: LED2.2 96.749,-25.006 v2(96.749,-26.111)
NetLED3_2: LED3.2 R8.1 | length 5.1
  Top Layer w0.254: R8.1 113.832,-22.007 v2(114.097,-21.742)
  Bottom Layer w0.254: v2(114.097,-21.742) 114.097,-22.504 114.732,-23.139 114.732,-24.905 LED3.2
NetLED4_2: LED4.2 R9.1 | length 5.4
  Top Layer w0.508: R9.1 v1(75.338,-37.974)
  Mid-Layer 1 w0.508: v1(75.338,-37.974) v1(78.586,-37.974)
  Bottom Layer w0.508: LED4.2 78.575,-37.963 v1(78.586,-37.974)
NetLED5_2: LED5.2 R14.1 | length 30.3
  Top Layer w0.254: R14.1 111.796,-51.395 v2(111.81,-51.381)
  Mid-Layer 1 w0.254: v2(96.749,-35.484) 96.749,-38.024 100.422,-41.698 100.422,-44.688 101.124,-45.39 109.957,-45.39 111.81,-47.243 v2(111.81,-51.381)
  Bottom Layer w0.254: LED5.2 96.749,-36.855 v2(96.749,-35.484)
NetLED6_2: LED6.2 R15.1 | length 1.6
  Top Layer w0.254: R15.1 114.656,-35.509 v2(114.656,-36.195)
  Bottom Layer w0.254: v2(114.656,-36.195) 114.656,-36.944 LED6.2
NetLED7_2: LED7.2 R16.1 | length 6.6
  Top Layer w0.508: R16.1 81.929,-49.058 v1(82.117,-48.87)
  Bottom Layer w0.508: LED7.2 v1(82.117,-48.87)
NetLED8_2: LED8.2 R17.1 | length 9.7
  Top Layer w0.254: R17.1 91.843,-54.563 v2(91.843,-53.761)
  Bottom Layer w0.254: v2(91.843,-53.761) 91.843,-51.388 92.507,-50.724 95.91,-50.724 96.634,-50 LED8.2
NetLED9_2: LED9.2 R21.1 | length 11.3
  Top Layer w0.254: v3(114.503,-39.878) 114.503,-37.886 R21.1
  Bottom Layer w0.254: v3(114.503,-39.878) 114.503,-39.982 114.821,-40.3 LED9.2
NetLED10_2: LED10.2 R22.1 | length 4.6
  Top Layer w0.5: v2(81.737,-60.477) 81.798,-60.416 R22.1
  Bottom Layer w0.5: LED10.2 81.28,-60.935 v2(81.737,-60.477)
NetLED11_2: LED11.2 R26.1 | length 9.3
  Top Layer w0.254: R26.1 92.821,-56.718 92.821,-56.905 93.015,-57.098 v2(93.015,-57.165)
  Bottom Layer w0.254: v2(93.015,-57.165) 94.552,-57.165 94.872,-56.845 96.029,-56.845 96.66,-57.476 LED11.2
NetnRF1_1: nRF1.1 X1.1 | length 6
  Top Layer w0.254: X1.1 100.432,-57.175 100.882,-56.725 nRF1.1
NetnRF1_2: nRF1.2 X1.2 | length 5.9
  Top Layer w0.254: nRF1.2 101.382,-56.907 101.651,-57.175 X1.2
NetQ1_1: Q1.1 R4.2 R13.1 | length 3.3
  Top Layer w0.254: R13.1 117.886,-49.89 118.11,-50.114 Q1.1
NetQ1_3: Q1.3 R5.1 | length 1.7
  Top Layer w0.3: R5.1 119.659,-46.258 119.659,-47.795 Q1.3
NetQ2_B: Q2.B R18.1 R20.2 | length 6.7
  Top Layer w0.254: Q2.B 112.029,-49.083 112.033,-49.079 112.033,-45.873 112.182,-45.725 112.497,-45.725 R18.1 112.776,-45.496 R20.2
NetQ2_C: Q2.C R13.2 | length 2.9
  Top Layer w0.254: Q2.C 113.868,-47.828 114.63,-48.59 R13.2
NetQ3_B: Q3.B R19.1 R23.2 | length 3.7
  Top Layer w0.508: Q3.B 74.674,-50.328 74.771,-50.231 R23.2 76.478,-50.231 76.565,-50.317 R19.1
NetQ4_3: Q4.3 Q5.3 | length 2.3
  Top Layer w0.254: Q4.3 111.006,-60.975 111.006,-63.231 Q5.3
NetR5_2: R5.2 R7.1 R12.1 | length 4.1
  Top Layer w0.254: R7.1 117.13,-44.918 R12.1
NetR28_2: R28.2 U2.20 | length 3.7
  Top Layer w0.254: R28.2 82.271,-32.487 83.521,-33.737 U2.20
NetR29_2: R29.2 U2.19 | length 3.8
  Top Layer w0.254: R29.2 83.439,-30.332 83.439,-31.166 83.795,-31.521 83.795,-32.741 84.286,-33.232 84.773,-33.232 U2.19
NetR34_2: R34.2 U2.11 | length 2.7
  Top Layer w0.254: U2.11 89.834,-33.737 90.439,-33.132 90.881,-33.132 R34.2
NRESET: JP1.3 R24.1 | length 32.4
  Top Layer w0.254: R24.1 107.874,-41.777 107.975,-41.675 v2(107.975,-41.148)
  Mid-Layer 1 w0.254: JP1.3 97.133,-17.53 97.794,-17.53 98.171,-17.907 98.171,-32.546 102.333,-36.708 102.333,-39.497 102.485,-39.649 107.34,-39.649 107.975,-40.284 v2(107.975,-41.148)
RESET: C6.2 JP1.4 nRF1.30 R24.2 | length 35.8
  Top Layer w0.254: nRF1.30 103.882,-44.399 104.369,-43.913 104.369,-43.028 104.953,-42.443 106.156,-42.443 106.305,-42.295 106.305,-42.016 R24.2 v2(106.559,-40.998) C6.2
  Mid-Layer 1 w0.254: JP1.4 96.876,-23.132 96.705,-23.132 95.504,-24.333 95.504,-30.521 101.879,-36.896 101.879,-40.361 102.516,-40.998 v2(106.559,-40.998)
RF: C4.2 L3.2 | length 25.7
  Top Layer w0.254: L3.2 103.375,-29.918
  Top Layer w0.8: 101.117,-27.661 103.375,-29.918
  Top Layer w1.5: 101.117,-27.661 101.117,-21.666 102.972,-19.812 114.808,-19.812
SCL: nRF1.8 R31.1 U2.17 | length 41.8
  Top Layer w0.2: nRF1.8 104.382,-53.275 104.991,-53.884 104.991,-54.423 v2(105.002,-54.434)
  Top Layer w0.254: v2(86.002,-31.245) 86.015,-31.258 v2@86.028,-31.258 ; U2.17 86.028,-31.261 86.031,-31.258 v2@86.028,-31.258 ; R31.1 86.393,-30.477 86.393,-30.828 86.028,-31.193 v2@86.028,-31.258
  Mid-Layer 1 w0.254: v2(86.002,-31.245) 86.002,-32.306 86.233,-32.537 88.715,-32.537 95.761,-39.584 95.761,-52.212 96.527,-52.978 104.184,-52.978 105.029,-53.823 105.029,-54.407 v2(105.002,-54.434)
SDA: nRF1.7 R30.1 U2.18 | length 41.3
  Top Layer w0.2: nRF1.7 103.882,-53.406 104.292,-53.816 v2(104.292,-54.559)
  Top Layer w0.254: R30.1 85.09,-30.307 v2@85.09,-31.318 ; v2@85.158,-31.386 85.528,-31.757 U2.18
  Mid-Layer 1 w0.254: v2(85.125,-31.418) 85.125,-32.395 85.827,-33.096 88.632,-33.096 95.307,-39.772 95.307,-52.4 96.339,-53.432 103.165,-53.432 v2(104.292,-54.559)
SW: nRF1.41 R25.2 | length 18.8
  Top Layer w0.203: v2@98.906,-48.17 nRF1.41 ; v2(111.857,-53.747) 111.857,-54.412 R25.2
  Mid-Layer 1 w0.203: v2(98.745,-48.089) 99.194,-48.089 99.593,-48.489 99.593,-50.825 100.006,-51.238 107.423,-51.238 109.986,-53.801 111.803,-53.801 v2(111.857,-53.747)
SWDCLK: JP1.6 nRF1.26 | length 37.2
  Top Layer w0.254: nRF1.26 105.882,-45.058 105.905,-45.035 105.905,-44.873 106.491,-44.287 106.497,-44.287 106.817,-43.967 107.754,-43.967 107.983,-43.739 v2(108.026,-43.739)
  Mid-Layer 1 w0.254: JP1.6 94.336,-29.994 101.33,-36.989 101.33,-43.596 102.207,-44.473 107.038,-44.473 107.725,-43.786 107.979,-43.786 v2(108.026,-43.739)
SWDIO: JP1.8 nRF1.25 | length 38.8
  Top Layer w0.254: nRF1.25 106.382,-45.074 107.032,-44.425 107.939,-44.425 107.961,-44.403 108.31,-44.403 v2(108.357,-44.356)
  Mid-Layer 1 w0.254: JP1.8 92.024,-20.041 92.024,-23.647 92.888,-24.511 92.888,-29.718 100.876,-37.707 100.876,-44.276 101.528,-44.927 107.786,-44.927 v2(108.357,-44.356)
SWO: JP1.10 nRF1.18 | length 45.1
  Top Layer w0.254: nRF1.18 108.879,-49.17 108.9,-49.149 v2(108.966,-49.149)
  Mid-Layer 1 w0.254: JP1.10 89.256,-22.555 91.288,-24.587 91.291,-24.587 91.44,-24.736 91.44,-29.7 95.71,-33.97 95.71,-37.678 99.212,-41.18 99.212,-44.12 100.936,-45.844 109.63,-45.844 109.779,-45.993 109.779,-47.85 109.025,-48.604 109.025,-49.149 v2(108.966,-49.149)
TK01: CN1.3 U2.1 | length 10.5
  Top Layer w0.203: U2.1 85.528,-37.684 85.141,-38.072 84.407,-38.072 83.388,-39.091 83.388,-42.765 83.693,-43.069 CN1.3@85.712,-43.069
  Top Layer w0.508: CN1.3@85.712,-43.069 85.952,-43.069 85.953,-43.069 CN1.3@86.199,-43.069
TK02: CN1.5 U2.23 | length 16.1
  Top Layer w0.203: U2.23 83.712,-35.237 81.915,-37.033 81.915,-45.009 82.516,-45.609 CN1.5@85.712,-45.609
  Top Layer w0.508: CN1.5@85.712,-45.609 85.952,-45.609 85.953,-45.609 CN1.5@86.199,-45.609
TK03: CN1.7 U2.9 | length 19.3
  Top Layer w0.203: CN1.7@87.969,-46.879 92.033,-46.879 92.608,-46.304 92.608,-37.313 90.032,-34.737 U2.9
  Top Layer w0.508: CN1.7@87.482,-46.879 87.483,-46.879 CN1.7@87.969,-46.879
TK04: CN1.9 U2.7 | length 12.9
  Top Layer w0.203: CN1.9@87.969,-44.339 90.585,-44.339 91.161,-43.764 91.161,-38.913 88.778,-36.531 U2.7
  Top Layer w0.508: CN1.9@87.482,-44.339 87.483,-44.339 CN1.9@87.969,-44.339
TK05: CN1.11 U2.5 | length 8.9
  Top Layer w0.203: U2.5 87.528,-38.481 87.909,-38.862 88.9,-38.862 89.713,-39.675 89.713,-41.631 89.544,-41.799 CN1.11@87.969,-41.799
  Top Layer w0.508: CN1.11@87.482,-41.799 87.483,-41.799 CN1.11@87.969,-41.799
TK06: CN1.2 U2.2 | length 8.8
  Top Layer w0.203: CN1.2@85.712,-41.799 85.703,-41.808 84.303,-41.808 84.049,-41.554 84.049,-39.548 84.76,-38.837 85.801,-38.837 86.028,-38.609 U2.2
  Top Layer w0.508: CN1.2@85.712,-41.799 85.952,-41.799 85.953,-41.799 CN1.2@86.199,-41.799
TK07: CN1.10 U2.6 | length 11
  Top Layer w0.203: CN1.10@87.969,-43.069 90.281,-43.069 90.5,-42.85 90.5,-39.243 89.306,-38.049 88.417,-38.049 88.028,-37.66 U2.6
  Top Layer w0.508: CN1.10@87.482,-43.069 87.483,-43.069 CN1.10@87.969,-43.069
TK08: CN1.8 U2.8 | length 16.1
  Top Layer w0.203: CN1.8@87.969,-45.609 91.068,-45.609 91.973,-44.704 91.973,-37.617 89.593,-35.237 U2.8
  Top Layer w0.508: CN1.8@87.482,-45.609 87.483,-45.609 CN1.8@87.969,-45.609
TK09: CN1.6 U2.22 | length 19.3
  Top Layer w0.203: U2.22 82.789,-34.737 81.28,-36.246 81.28,-46.279 81.881,-46.879 CN1.6@85.712,-46.879
  Top Layer w0.508: CN1.6@85.712,-46.879 85.952,-46.879 85.953,-46.879 CN1.6@86.199,-46.879
TK10: CN1.4 U2.24 | length 12.7
  Top Layer w0.203: U2.24 84.778,-36.481 82.702,-38.557 82.702,-43.917 83.125,-44.339 CN1.4@85.712,-44.339
  Top Layer w0.508: CN1.4@85.712,-44.339 85.952,-44.339 85.953,-44.339 CN1.4@86.199,-44.339
TK11: CN1.1 U2.3 | length 4.8
  Top Layer w0.203: CN1.1@85.712,-40.529 85.865,-40.529 86.182,-40.212 86.182,-39.446 86.528,-39.1 U2.3
  Top Layer w0.508: CN1.1@85.865,-40.529 85.952,-40.529 85.953,-40.529 CN1.1@86.199,-40.529
TK12: CN1.12 U2.4 | length 4.9
  Top Layer w0.203: U2.4 87.028,-38.972 87.541,-39.484 87.541,-40.212 87.858,-40.529 CN1.12@87.969,-40.529
  Top Layer w0.508: CN1.12@87.482,-40.529 87.483,-40.529 CN1.12@87.858,-40.529
VCC_3V3: LED1.1 LED2.1 LED3.1 LED4.1 LED5.1 LED6.1 LED7.1 LED8.1 LED9.1 LED10.1 LED11.1 LED12.1 | length 173.1
  Top Layer w0.508: v1(76.986,-36.12) 76.427,-35.561 76.427,-24.639 v1(77.087,-23.979)
  Mid-Layer 2 w0.508: v1(112.343,-61.486) 113.157,-60.672 113.157,-54.288 113.968,-53.477 v1(113.968,-47.093)
  Bottom Layer w0.508: LED4.1 76.975,-36.131 v1(76.986,-36.12) ; LED10.1 77.051,-54.916 77.038,-54.903 LED7.1 77.038,-48.236 77.369,-47.906 83.031,-47.906 84.147,-49.022 LED8.1 95.047,-42.991 LED5.1 95.047,-32.131 96.457,-30.721 96.457,-28.449 ; LED1.1 v1@77.076,-23.99 ; v1(77.087,-23.979) v1@77.076,-23.99 ; LED11.1 95.06,-61.738 95.274,-61.952 97.306,-61.952 101.498,-57.76 108.227,-57.76 111.953,-61.486 v1(112.343,-61.486) LED12.1 ; LED9.1 113.221,-47.73 114.029,-46.921 114.029,-46.5 113.919,-46.39 113.919,-41.25 113.094,-40.424 LED6.1 LED3.1 108.89,-24.943 107.821,-26.011 107.821,-27.103 106.475,-28.449 96.457,-28.449 ; v1@77.076,-23.99 77.076,-21.998 90.981,-21.82 94.13,-24.968 LED2.1 95.11,-27.103 96.457,-28.449
"VDD nRF": C8.2 C9.2 C10.2 C11.2 C12.1 C17.2 C18.2 C19.2 C21.2 C22.2 C24.2 JP1.1 nRF1.10 nRF1.22 nRF1.36 nRF1.47 nRF1.48 R30.2 R31.2 R32.2 U2.13 U2.14 U3.3 | length 128.6
  Top Layer w0.203: U2.14 U2.13 88.443,-32.487 88.798,-32.131 89.484,-32.131 90.018,-31.598 90.674,-31.598 v1(90.678,-31.594) ; C12.1 C9.2@97.388,-45.318 ; C8.2 C9.2 C9.2@97.388,-45.318 ; nRF1.47@100.132,-51.27 nRF1.47 ; nRF1.36 97.49,-45.42 C9.2@97.388,-45.318 ; nRF1.10 105.382,-53.134 106.324,-54.077 106.324,-55.855 v2(106.782,-56.312)
  Top Layer w0.254: R30.2 85.141,-28.905 88.163,-28.905 89.637,-28.905 C19.2 91.567,-28.89 C18.2 ; C10.2 97.795,-54.234 C24.2 ; nRF1.22 107.141,-47.162 107.873,-47.162 108.553,-46.482 v1(108.915,-46.482)
  Top Layer w0.5: U3.3 94.231,-60.161 94.524,-59.868 97.307,-59.868 97.739,-59.436 C11.2 C10.2 97.87,-54.047 98.116,-54.047 98.163,-54 99.839,-54 100.132,-53.708 nRF1.48 nRF1.47@100.132,-51.27
  Top Layer w0.508: R30.2 88.163,-28.981 89.56,-28.981 89.637,-28.905 89.687,-28.854 v1(90.754,-28.854) ; v1(92.946,-35.342) 93.732,-35.342 94.249,-34.825 ; C22.2 94.249,-34.825 ; C8.2 97.388,-43.06 97.103,-42.775 95.096,-42.775 94.249,-41.928 94.249,-34.825
  Mid-Layer 1 w0.203: v2(106.782,-56.312) 107.569,-56.312 108.128,-55.753 110.631,-55.753 111.415,-54.969 112.09,-54.294 112.573,-53.811 112.573,-52.57 112.454,-52.451 111.404,-52.451 109.305,-50.352 109.292,-50.352 107.747,-48.807 107.747,-46.601 107.866,-46.482 v1(108.915,-46.482)
  Mid-Layer 2 w0.508: v1(90.678,-31.594) 90.678,-31.854 90.727,-31.904 ; v1(92.946,-35.342) 90.727,-33.123 90.727,-31.904 ; JP1.1 98.144,-18.544 98.144,-24.772 97.846,-25.07 91.211,-25.07 90.727,-25.554 90.727,-31.904
  Bottom Layer w0.203: v2(97.42,-45.689) 97.42,-45.782 97.434,-45.797 97.434,-49.598 97.358,-49.675 97.358,-50.419 97.742,-50.803 v2(97.742,-56.41) 98.047,-56.715 100.484,-56.715 100.887,-56.312 v2(106.782,-56.312)
"VSS PA": C1.1 C3.1 C4.1 C5.1 C6.1 C7.1 C8.1 C9.1 C10.1 C11.1 C12.2 C13.1 C14.2 C15.2 C16.2 C18.1 C19.1 C20.1 C21.1 C23.1 C24.1 CN2.2 D2.1 D3.1 D4.1 D5.1 JP1.2 nRF1.32 nRF1.44 nRF1.49 Q2.E Q3.E Q4.1 Q5.1 R10.1 R11.1 R12.2 R20.1 R23.1 R28.1 R29.1 R33.2 R35.2 U1.2 U2.12 U3.1 | length 115.8
  Top Layer w0.203: U2.12 89.496,-33.237 90.537,-32.195 91.325,-32.195 91.719,-31.801 92.388,-31.801 92.507,-31.682 92.507,-30.673 R33.2 ; C16.2 C15.2 C12.2 C9.1 C8.1 ; nRF1.44 101.714,-49.67 101.803,-49.581 ; nRF1.32 102.882,-47.358 102.895,-47.371
  Top Layer w0.508: Q3.E 75.113,-48.428 R23.1 75.616,-45.923 75.806,-45.733 79.083,-45.733 ; C16.2 93.369,-52.021 93.369,-53.736 ; C24.1 96.495,-57.964 96.469,-57.939 C21.1 96.469,-56.44 96.439,-56.41 C11.1 C10.1 95.386,-54.178 95.223,-54.015 C7.1 93.648,-54.015 93.369,-53.736 ; JP1.2 99.416,-21.565 99.008,-21.972 92.569,-21.972 ; v1(99.637,-31.98) 98.449,-31.98 97.663,-32.766 R35.2 94.249,-31.725 R33.2 92.852,-29.618 C19.1 92.852,-28.17 92.867,-28.155 C18.1 92.867,-22.27 92.569,-21.972 ; 79.083,-45.733 79.083,-40.932 80.34,-39.675 R28.1 80.34,-30.354 81.713,-28.981 R29.1 83.49,-23.039 84.557,-21.972 92.569,-21.972 ; 79.083,-45.733 81.256,-47.906 87.538,-47.906 93.369,-53.736
  other v1: 73.935,-66.2 76.435,-66.2 78.935,-66.2 81.435,-66.2 83.935,-66.2 86.435,-66.2 88.935,-66.2 91.435,-66.2 93.935,-66.2 98.935,-66.2 101.435,-66.2 103.935,-66.2 106.435,-66.2 108.935,-66.2 113.935,-66.2 116.435,-66.2 75.185,-63.7 77.685,-63.7 85.185,-63.7 90.185,-63.7 92.685,-63.7 102.685,-63.7 107.685,-63.7 112.685,-63.7 117.685,-63.7 71.435,-61.2 73.935,-61.2 91.435,-61.2 108.935,-61.2 116.435,-61.2 118.935,-61.2 72.685,-58.7 75.185,-58.7 90.185,-58.7 92.685,-58.7 95.185,-58.7 102.685,-58.7 107.685,-58.7 117.685,-58.7 73.935,-56.2 115.185,-53.7 117.685,-53.7 73.935,-51.2 81.435,-51.2 83.935,-51.2 86.435,-51.2 88.935,-51.2 116.435,-51.2 118.935,-51.2 103.632,-48.92 72.685,-48.7 102.685,-48.7 105.185,-48.7 121.183,-47.523 71.435,-46.2 73.935,-46.2 76.435,-46.2 72.685,-43.7 75.185,-43.7 77.685,-43.7 117.685,-43.7 71.435,-41.2 73.935,-41.2 76.435,-41.2 116.435,-41.2 72.685,-38.7 100.185,-38.7 105.185,-38.7 107.685,-38.7 115.185,-38.7 71.435,-36.2 73.935,-36.2 116.435,-36.2 72.685,-33.7 75.185,-33.7 77.685,-33.7 105.185,-33.7 107.685,-33.7 115.185,-33.7 71.435,-31.2 73.935,-31.2 98.935,-31.2 101.435,-31.2 106.435,-31.2 116.435,-31.2 72.685,-28.7 75.185,-28.7 80.185,-28.7 115.185,-28.7 71.435,-26.2 73.935,-26.2 81.435,-26.2 83.935,-26.2 98.935,-26.2 72.685,-23.7 75.185,-23.7 80.185,-23.7 82.685,-23.7 95.185,-23.7 71.435,-21.2 73.935,-21.2 76.435,-21.2 78.935,-21.2 98.935,-21.2 77.685,-18.7 80.185,-18.7 82.685,-18.7 85.185,-18.7 87.685,-18.7
XC1: nRF1.34 X2.1 | length 6
  Top Layer w0.203: X2.1 99.162,-43.256 99.644,-43.739 101.016,-43.739 101.882,-44.605 nRF1.34
XC2: nRF1.35 X2.3 | length 11.5
  Top Layer w0.203: X2.3@96.511,-37.827 97.942,-39.258 97.942,-42.672 98.349,-43.078 98.349,-44.044 98.755,-44.45 101.013,-44.45 101.382,-44.819 nRF1.35
  Top Layer w0.508: X2.3@96.511,-37.827 96.511,-37.771 96.74,-37.771 X2.3
pads on no net: BUZ1. JP1.5 JP1.7 JP1.9 nRF1.3 nRF1.4 nRF1.37 nRF1.38 U2.25 X2.2 X2.4

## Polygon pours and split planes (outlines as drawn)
"VSS PA" on Top Layer "Top Layer-No Net" (solid, remove dead copper, pour order 1): 70.353,-66.388 cw(c70.831,-64.793) 69.301,-65.452 69.301,-20.62 cw(c95.728,-93.172) 122.567,-20.772 122.567,-65.212 cw(c121.341,-65.029) 121.523,-66.256 cw(c96.719,100.307) 94.816,-68.082 cw(c94.76,92.142) 86.241,-67.855 cw(c97.151,137.032)
NetQ4_3 on Top Layer "NONET_L04_P-001" (solid, remove dead copper, pour order 0): 111.227,-60.452 110.058,-60.452 109.88,-60.63 109.88,-63.551 110.109,-63.779 111.455,-63.779 111.582,-63.652 111.582,-60.706 111.379,-60.503
"VSS PA" on Bottom Layer "Top Layer-No Net1" (solid, remove dead copper, pour order 2): 70.353,-66.388 cw(c70.831,-64.793) 69.301,-65.452 69.301,-20.62 cw(c95.728,-93.172) 122.567,-20.772 122.567,-65.212 cw(c121.341,-65.029) 121.523,-66.256 cw(c96.719,100.307) 94.816,-68.082 cw(c94.76,92.142) 86.241,-67.855 cw(c97.151,137.032)

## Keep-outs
Keep-Out Layer:
  circle w0.127: c104.857,-25.05 r2.542
  circle w0.127: c104.857,-61.091 r2.542
  circle w0.127: c86.918,-61.091 r2.542
  circle w0.127: c86.918,-25.05 r2.542
  lines w0.127: 122.567,-65.212 cw(c121.341,-65.029) 121.523,-66.256 cw(c96.719,100.307) 94.816,-68.082 cw(c94.76,92.142) 86.241,-67.855 cw(c97.151,137.032) 70.353,-66.388 cw(c70.831,-64.793) 69.301,-65.452 69.301,-20.62 cw(c95.728,-93.172) 122.567,-20.772 122.567,-65.207

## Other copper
Multi-Layer:
  pour cut-out: 78.664,-50.444 95.199,-50.444 95.25,-50.495 95.25,-29.845 79.07,-29.845 78.664,-30.251
  pour cut-out: 102.596,-42.337 102.418,-42.159 cw(c102.489,-42.088) 102.389,-42.088 102.389,-31.411 100.386,-29.408 cw(c100.457,-29.337) 100.357,-29.337 100.357,-15.951 cw(c100.457,-15.951) 100.557,-15.951 100.557,-29.295 102.56,-31.298 cw(c102.489,-31.369) 102.589,-31.369 102.589,-42.046 102.708,-42.165 103.862,-42.165 103.862,-29.591 cw(c103.962,-29.591) 103.891,-29.52 104.069,-29.342 cw(c104.14,-29.413) 104.14,-29.313 107.146,-29.313 107.443,-29.016 107.443,-23.393 cw(c107.544,-23.393) 107.473,-23.322 107.773,-23.022 107.773,-21.641 cw(c107.874,-21.641) 107.803,-21.57 108.108,-21.265 cw(c108.179,-21.336) 108.179,-21.236 122.504,-21.236 cw(c122.504,-21.336) 122.605,-21.336 cw(c122.504,-21.336) 122.504,-21.436 108.22,-21.436 107.974,-21.682 107.974,-23.063 cw(c107.874,-23.063) 107.945,-23.134 107.644,-23.435 107.644,-29.058 cw(c107.544,-29.058) 107.615,-29.129 107.259,-29.484 cw(c107.188,-29.413) 107.188,-29.514 104.182,-29.514 104.063,-29.633 104.063,-42.266 cw(c103.962,-42.266) 103.962,-42.366 102.667,-42.366 cw(c102.667,-42.266)
  lines w0.2: 122.504,-21.336 122.555,-21.387

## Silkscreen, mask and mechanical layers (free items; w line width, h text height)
Top Overlay:
  lines w0.2: 95.199,-50.444 95.275,-50.521 95.25,-50.495
  text "20240429" at 83.541,-65.202 h1.15
  text "LY-HL669-V1.0" at 82.372,-67.031 h1.15
  text "YEZHIQUAN-LS" at 95.555,-67.031 h1.15
Bottom Overlay:
  drawing of 1533 lines, arcs and shapes, not listed
Mechanical 5:
  lines w0.127: -121.455,-118.105 -121.446,-118.174 ; -117.133,-118.174 -117.124,-118.105

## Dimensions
69.301,-20.62 to 122.567,-20.772 on Bottom Solder
95.728,-15.957 to 96.719,-68.093 on Bottom Solder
